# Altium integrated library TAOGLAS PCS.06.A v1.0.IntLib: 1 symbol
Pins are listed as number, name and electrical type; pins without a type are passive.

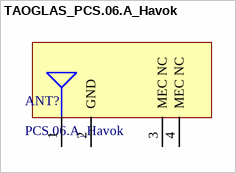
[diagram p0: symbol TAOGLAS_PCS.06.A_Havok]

## TAOGLAS_PCS.06.A_Havok
designator ANT?, comment PCS.06.A_Havok
Havok - Low Profile LTE/Cellular 4G/3G/2G SMD Dielectric Antenna ¦ 698~960MHz/1710~2690MHz; ComponentLibStatus: Created; MFG: Taoglas; Temp_High: +85C; Temp_Low: -40C
footprint TAOGLAS_PCS.06.A_Havok (Havok - Low Profile LTE/Cellular 4G/3G/2G SMD  Dielectric Antenna)
pins: 1 RF OUT, 2 GND, 3 MEC NC, 4 MEC NC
